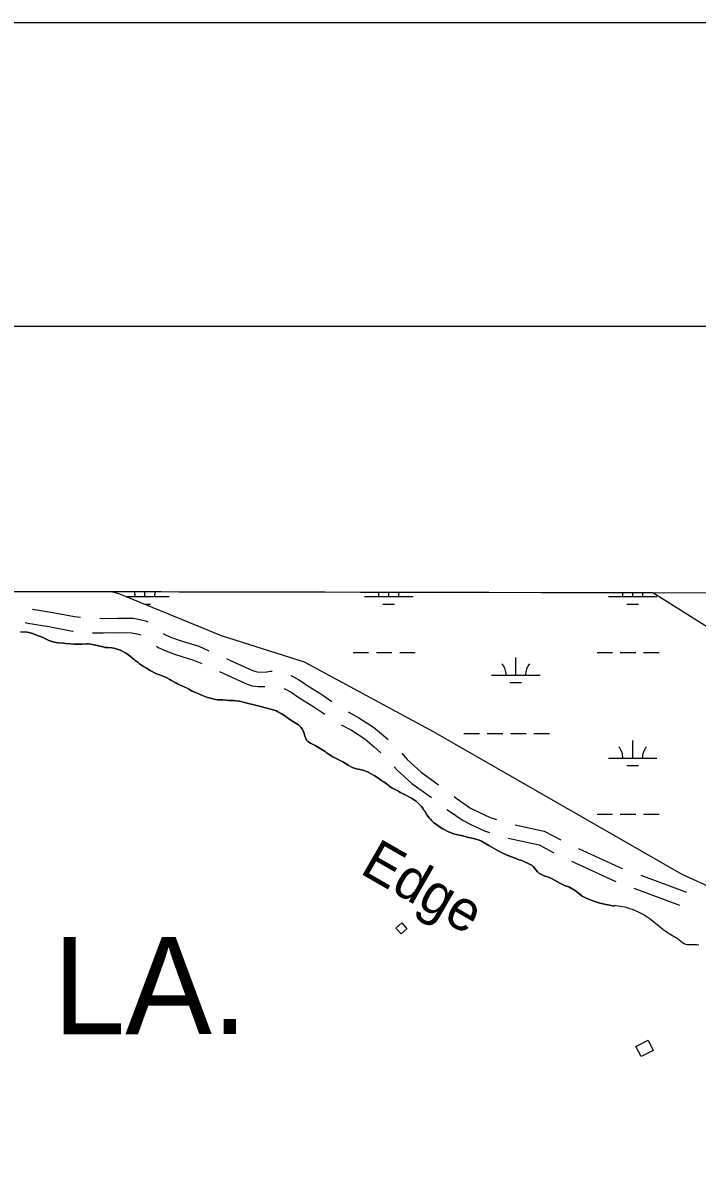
# Model space of a CAD drawing. Extents: x 3192927 to 3230760, y 831141 to 856475.
# Drawn here: x 3203837 to 3205224, y 853534 to 855891 of the extents above; entities that cross this region are included whole.
import ezdxf

# ---------------------------------------------------------------- set-up
doc = ezdxf.new("R2010")
doc.units = 0
for name, color, linetype in [('G-ANNO-NPLT', 7, 'Continuous'), ('V-ANNO-SYMB', 7, 'Continuous'), ('V-BLDG-OTLN', 7, 'Continuous'), ('V-GRID-FRAM', 7, 'Continuous'), ('V-RIVR-IDEN', 7, 'Continuous'), ('V-ROAD-CNTR', 7, 'Continuous'), ('V-SITE-VEGE', 7, 'Continuous'), ('V-TOPO-GNAM-IDEN', 7, 'Continuous'), ('V-TOPO-SHOR', 7, 'Continuous'), ('V-WETL-SWMP', 7, 'Continuous')]:
    doc.layers.add(name, color=color, linetype=linetype)

msp = doc.modelspace()

# ---------------------------------------------------------------- linework, layer by layer
at = {"layer": 'G-ANNO-NPLT'}
msp.add_lwpolyline([(3193509.9, 831724.7), (3230176.5, 831724.7), (3230176.5, 855891.4), (3193509.9, 855891.4)], close=True, dxfattribs=at)
at = {"layer": 'V-ANNO-SYMB'}
msp.add_lwpolyline([(3196260, 832349.8), (3229343.2, 832349.8), (3229343.2, 855266.3), (3196260, 855266.3), (3196260, 832349.8)], dxfattribs=at)
at = {"layer": 'V-BLDG-OTLN'}
for points in [[(3204604.9, 854027.6), (3204616.9, 854038.5), (3204627.2, 854025.9), (3204615.8, 854015.6)], [(3205098.7, 853784.2), (3205123.7, 853796.6), (3205134, 853775.9), (3205109.1, 853763.5)]]:
    msp.add_lwpolyline(points, close=True, dxfattribs=at)
at = {"layer": 'V-GRID-FRAM'}
msp.add_lwpolyline([(3197144.3, 854733.3), (3228527.7, 854674), (3228501.2, 836486.7), (3197102, 836546.1), (3197144.3, 854733.3)], dxfattribs=at)
at = {"layer": 'V-ROAD-CNTR'}
for p, q in [((3205108.8, 854136.4), (3205202.4, 854101.3)), ((3205094.4, 854109.8), (3205188.1, 854074.7))]:
    msp.add_line(p, q, dxfattribs=at)
for points in [[(3203856.9, 854684.3), (3203895.6, 854678.1), (3203943.4, 854669), (3203955.5, 854667.9)], [(3203995.4, 854665.5), (3204002.2, 854665.4), (3204032.3, 854666), (3204064.3, 854665.7), (3204078, 854663.2), (3204083, 854662), (3204089.9, 854660), (3204094.4, 854658.2)], [(3203842.2, 854656.7), (3203847.2, 854655.5), (3203890.5, 854648.5), (3203939.2, 854639.3), (3203940.6, 854639.1)], [(3203980.5, 854635.7), (3204002.3, 854635.4), (3204032.4, 854636), (3204061.4, 854635.7), (3204072, 854633.8), (3204075.3, 854633), (3204080, 854631.6), (3204080, 854631.6)], [(3204126.4, 854634.4), (3204130.5, 854631.4), (3204142.8, 854626), (3204160.5, 854619.6), (3204199, 854607.8), (3204219.5, 854598.7)], [(3204111.9, 854607.8), (3204115.6, 854605.2), (3204131.6, 854598.2), (3204151, 854591.1), (3204188.5, 854579.6), (3204205.1, 854572.3)], [(3204256, 854582.5), (3204264.6, 854578.7), (3204309.7, 854558.1), (3204316.4, 854555.7), (3204322.5, 854554.8), (3204339, 854555.6), (3204346.8, 854556.7), (3204350.2, 854556.7)], [(3204241.7, 854556.1), (3204252.3, 854551.4), (3204298.4, 854530.2), (3204309.2, 854526.5), (3204321, 854524.8), (3204335.3, 854525.4)], [(3204388.5, 854547.6), (3204390, 854547), (3204404.4, 854539.2), (3204421.6, 854527.6), (3204452.3, 854508.5), (3204473.1, 854494.5)], [(3204374.1, 854521), (3204377.3, 854519.7), (3204388.9, 854513.5), (3204405.2, 854502.5), (3204436, 854483.4), (3204458.7, 854468)], [(3204506.7, 854472.9), (3204528.7, 854460.7), (3204558.5, 854441.2), (3204579.3, 854423.9), (3204588.5, 854415.8)], [(3204492.4, 854446.5), (3204513.2, 854435), (3204540.6, 854417.1), (3204559.8, 854401.1), (3204573.8, 854388.8)], [(3204616.6, 854387.5), (3204628.1, 854374.5), (3204656.5, 854348.9), (3204692.5, 854322.9)], [(3204601.1, 854359.7), (3204606.8, 854353.3), (3204637.6, 854325.6), (3204678.1, 854296.3)], [(3204724.3, 854298.7), (3204730.7, 854293.7), (3204758.4, 854274.8), (3204773.7, 854267), (3204798.5, 854255.7), (3204811.6, 854251)], [(3204709.8, 854271.9), (3204712.9, 854269.5), (3204743.1, 854249), (3204760.6, 854240), (3204787.2, 854227.8), (3204797.2, 854224.3)], [(3204850.1, 854240.3), (3204909.6, 854227.2), (3204944.2, 854209.1)], [(3204835.5, 854212.8), (3204899.2, 854198.8), (3204930, 854182.7)], [(3204980.3, 854191.8), (3205063.8, 854153.3), (3205071.3, 854150.5)], [(3204966, 854165.3), (3205052.2, 854125.6), (3205057, 854123.8)]]:
    msp.add_lwpolyline(points, dxfattribs=at)
at = {"layer": 'V-SITE-VEGE'}
for p, q in [((3205133.2, 854718.2), (3203566.3, 854721.2)), ((3205617.6, 854411.2), (3205133.2, 854718.2)), ((3203832.4, 854637.6), (3203845.8, 854636.7)), ((3203845.8, 854636.7), (3203849.6, 854636.2)), ((3203849.6, 854636.2), (3203854.9, 854634.7)), ((3203854.9, 854634.7), (3203864.1, 854631.6)), ((3203864.1, 854631.6), (3203876.8, 854626.4)), ((3203876.8, 854626.4), (3203890.9, 854619.8)), ((3203890.9, 854619.8), (3203899, 854617)), ((3203899, 854617), (3203902, 854616.2)), ((3203902, 854616.2), (3203909.9, 854615.1)), ((3203909.9, 854615.1), (3203921.2, 854614)), ((3203921.2, 854614), (3203925, 854613.5)), ((3203925, 854613.5), (3203934.7, 854613)), ((3203934.7, 854613), (3203943.6, 854612.1)), ((3203958.6, 854612.3), (3203969.2, 854613)), ((3203969.2, 854613), (3203972.4, 854613)), ((3203972.4, 854613), (3203976.8, 854612.3)), ((3203943.6, 854612.1), (3203958.6, 854612.3)), ((3203976.8, 854612.3), (3203983.1, 854610.8)), ((3203983.1, 854610.8), (3203986.9, 854610)), ((3203986.9, 854610), (3203990, 854609.7)), ((3203990, 854609.7), (3204001.7, 854606.6)), ((3204001.7, 854606.6), (3204006.3, 854605.7)), ((3204006.3, 854605.7), (3204011.4, 854605.3)), ((3204011.4, 854605.3), (3204020, 854604.5)), ((3204020, 854604.5), (3204024.3, 854603.7)), ((3204024.3, 854603.7), (3204031.5, 854602)), ((3204031.5, 854602), (3204035.2, 854600.9)), ((3204035.2, 854600.9), (3204039.2, 854599.1)), ((3204039.2, 854599.1), (3204048.7, 854593.7)), ((3204048.7, 854593.7), (3204052.3, 854591.4)), ((3204052.3, 854591.4), (3204065.5, 854581.2)), ((3204065.5, 854581.2), (3204068.1, 854578.9)), ((3204068.1, 854578.9), (3204074.1, 854574.2)), ((3204074.1, 854574.2), (3204077.1, 854571.7)), ((3204077.1, 854571.7), (3204085.6, 854566.2)), ((3204085.6, 854566.2), (3204091.4, 854562.7)), ((3204091.4, 854562.7), (3204099.2, 854558.1)), ((3204099.2, 854558.1), (3204110.7, 854552.1)), ((3204110.7, 854552.1), (3204118, 854549.2)), ((3204118, 854549.2), (3204122, 854547.9)), ((3204122, 854547.9), (3204129.5, 854544.8)), ((3204129.5, 854544.8), (3204133.3, 854543)), ((3204133.3, 854543), (3204139.5, 854539.5)), ((3204139.5, 854539.5), (3204143.3, 854537.2)), ((3204143.3, 854537.2), (3204147.7, 854534.7)), ((3204147.7, 854534.7), (3204152, 854532.4)), ((3204152, 854532.4), (3204155.2, 854530.8)), ((3204155.2, 854530.8), (3204158.2, 854529.1)), ((3204158.2, 854529.1), (3204170.3, 854523.5)), ((3204170.3, 854523.5), (3204174.1, 854522.1)), ((3204174.1, 854522.1), (3204178.7, 854519.4)), ((3204178.7, 854519.4), (3204185.8, 854515.5)), ((3204185.8, 854515.5), (3204189, 854514)), ((3204189, 854514), (3204200.5, 854509.2)), ((3204200.5, 854509.2), (3204203.5, 854508.2)), ((3204203.5, 854508.2), (3204217, 854502.6)), ((3204217, 854502.6), (3204220.6, 854501.7)), ((3204220.6, 854501.7), (3204228.3, 854500)), ((3204228.3, 854500), (3204233.5, 854498.5)), ((3204233.5, 854498.5), (3204237.8, 854497.5)), ((3204237.8, 854497.5), (3204248.9, 854497.3)), ((3204248.9, 854497.3), (3204256.4, 854496.7)), ((3204256.4, 854496.7), (3204260, 854496.6)), ((3204260, 854496.6), (3204263.1, 854496.2)), ((3204263.1, 854496.2), (3204266.9, 854496.3)), ((3204266.9, 854496.3), (3204270.5, 854496.1)), ((3204270.5, 854496.1), (3204274.6, 854495.6)), ((3204274.6, 854495.6), (3204282.7, 854495.1)), ((3204282.7, 854495.1), (3204295.6, 854491.6)), ((3204295.6, 854491.6), (3204306.7, 854489)), ((3204306.7, 854489), (3204310.3, 854487.8)), ((3204310.3, 854487.8), (3204318, 854485.8)), ((3204318, 854485.8), (3204321.6, 854485)), ((3204321.6, 854485), (3204328.7, 854483.1)), ((3204328.7, 854483.1), (3204339, 854480.8)), ((3204339, 854480.8), (3204349.1, 854478)), ((3204349.1, 854478), (3204352.3, 854477.2)), ((3204352.3, 854477.2), (3204358.9, 854474.7)), ((3204358.9, 854474.7), (3204362, 854473.2)), ((3204362, 854473.2), (3204368.4, 854469.5)), ((3204368.4, 854469.5), (3204378.4, 854463.1)), ((3204378.4, 854463.1), (3204381.4, 854460.8)), ((3204381.4, 854460.8), (3204388.7, 854455.9)), ((3204388.7, 854455.9), (3204394.3, 854452)), ((3204394.3, 854452), (3204404.1, 854446)), ((3204404.1, 854446), (3204409.3, 854441.1)), ((3204409.3, 854441.1), (3204412.1, 854437.6)), ((3204412.1, 854437.6), (3204415.5, 854430.7)), ((3204415.5, 854430.7), (3204417.6, 854423.2)), ((3204417.6, 854423.2), (3204420.6, 854414.7)), ((3204420.6, 854414.7), (3204423.4, 854411.6)), ((3204423.4, 854411.6), (3204429.2, 854408.3)), ((3204429.2, 854408.3), (3204438.9, 854403.7)), ((3204438.9, 854403.7), (3204441.7, 854401.7)), ((3204441.7, 854401.7), (3204459, 854391)), ((3204459, 854391), (3204461.4, 854389.1)), ((3204461.4, 854389.1), (3204465.4, 854386.4)), ((3204465.4, 854386.4), (3204475.2, 854380.1)), ((3204475.2, 854380.1), (3204495.2, 854370.3)), ((3204495.2, 854370.3), (3204506.6, 854363.1)), ((3204506.6, 854363.1), (3204511, 854360.6)), ((3204511, 854360.6), (3204517.1, 854357.7)), ((3204517.1, 854357.7), (3204523.9, 854355.4)), ((3204523.9, 854355.4), (3204527.4, 854354.8)), ((3204527.4, 854354.8), (3204530.6, 854354.1)), ((3204530.6, 854354.1), (3204534.8, 854353.3)), ((3204534.8, 854353.3), (3204538.4, 854352.2)), ((3204538.4, 854352.2), (3204546.1, 854349.3)), ((3204546.1, 854349.3), (3204554, 854345.6)), ((3204554, 854345.6), (3204561.2, 854341.5)), ((3204561.2, 854341.5), (3204570.4, 854335.3)), ((3204570.4, 854335.3), (3204576.1, 854330.8)), ((3204576.1, 854330.8), (3204579.7, 854328.9)), ((3204579.7, 854328.9), (3204582.9, 854327)), ((3204582.9, 854327), (3204588.1, 854322.5)), ((3204588.1, 854322.5), (3204593.1, 854318.6)), ((3204593.1, 854318.6), (3204596.5, 854316.4)), ((3204596.5, 854316.4), (3204610, 854309.3)), ((3204610, 854309.3), (3204613.8, 854306.9)), ((3204613.8, 854306.9), (3204618.6, 854304.6)), ((3204618.6, 854304.6), (3204622.3, 854302.5)), ((3204622.3, 854302.5), (3204635.5, 854295.7)), ((3204635.5, 854295.7), (3204639, 854293.6)), ((3204639, 854293.6), (3204646.4, 854288.7)), ((3204646.4, 854288.7), (3204654.2, 854281.7)), ((3204654.2, 854281.7), (3204657.4, 854278)), ((3204657.4, 854278), (3204659.8, 854274.8)), ((3204659.8, 854274.8), (3204661.8, 854271.3)), ((3204661.8, 854271.3), (3204664, 854268.1)), ((3204664, 854268.1), (3204668.7, 854260.7)), ((3204668.7, 854260.7), (3204673.5, 854254.6)), ((3204673.5, 854254.6), (3204676.1, 854251.9)), ((3204676.1, 854251.9), (3204678.1, 854249.3)), ((3204678.1, 854249.3), (3204682.9, 854244.6)), ((3204682.9, 854244.6), (3204685.9, 854242.3)), ((3204685.9, 854242.3), (3204694.2, 854236.2)), ((3204694.2, 854236.2), (3204701, 854232.2)), ((3204701, 854232.2), (3204712.7, 854226)), ((3204712.7, 854226), (3204724.1, 854221.6)), ((3204724.1, 854221.6), (3204728.6, 854220.4)), ((3204728.6, 854220.4), (3204735.3, 854219.3)), ((3204735.3, 854219.3), (3204742.5, 854217.8)), ((3204742.5, 854217.8), (3204754, 854214.4)), ((3204754, 854214.4), (3204758.1, 854213.6)), ((3204758.1, 854213.6), (3204767.1, 854211.4)), ((3204767.1, 854211.4), (3204776.2, 854208.5)), ((3204776.2, 854208.5), (3204780.8, 854206.6)), ((3204780.8, 854206.6), (3204784.1, 854204.8)), ((3204784.1, 854204.8), (3204795.7, 854197.8)), ((3204795.7, 854197.8), (3204800.5, 854195.3)), ((3204800.5, 854195.3), (3204814.8, 854187)), ((3204814.8, 854187), (3204820.4, 854184.1)), ((3204820.4, 854184.1), (3204826.3, 854181.4)), ((3204826.3, 854181.4), (3204831.7, 854178.7)), ((3204831.7, 854178.7), (3204853.7, 854170.6)), ((3204853.7, 854170.6), (3204856.5, 854169.2)), ((3204856.5, 854169.2), (3204860.9, 854167.5)), ((3204860.9, 854167.5), (3204864, 854166.6)), ((3204864, 854166.6), (3204879.3, 854159.6)), ((3204879.3, 854159.6), (3204884.1, 854157.1)), ((3204884.1, 854157.1), (3204886.9, 854154.7)), ((3204886.9, 854154.7), (3204896.1, 854143.4)), ((3204896.1, 854143.4), (3204898.9, 854141)), ((3204898.9, 854141), (3204902.7, 854138.9)), ((3204902.7, 854138.9), (3204909.9, 854135.6)), ((3204909.9, 854135.6), (3204918.4, 854132.2)), ((3204918.4, 854132.2), (3204924.6, 854129.5)), ((3204924.6, 854129.5), (3204937.5, 854122.9)), ((3204937.5, 854122.9), (3204943.4, 854119.4)), ((3204943.4, 854119.4), (3204946.2, 854118.2)), ((3204946.2, 854118.2), (3204953.2, 854114.9)), ((3204953.2, 854114.9), (3204960.3, 854112.3)), ((3204960.3, 854112.3), (3204973.3, 854105.1)), ((3204973.3, 854105.1), (3204987.8, 854093.4)), ((3204987.8, 854093.4), (3204990.6, 854091.8)), ((3204990.6, 854091.8), (3204997.4, 854088.7)), ((3204997.4, 854088.7), (3205011.9, 854083.2)), ((3205011.9, 854083.2), (3205024, 854079.1)), ((3205024, 854079.1), (3205033.7, 854076.7)), ((3205033.7, 854076.7), (3205037, 854076.3)), ((3205037, 854076.3), (3205044.8, 854074.8)), ((3205044.8, 854074.8), (3205051.7, 854072.7)), ((3205051.7, 854072.7), (3205055.7, 854074.5)), ((3205055.7, 854074.5), (3205067.4, 854072.8)), ((3205067.4, 854072.8), (3205078.6, 854070.6)), ((3205078.6, 854070.6), (3205084.7, 854068.2)), ((3205084.7, 854068.2), (3205090.9, 854066.4)), ((3205090.9, 854066.4), (3205101.8, 854061.9)), ((3205101.8, 854061.9), (3205115.4, 854054.9)), ((3205115.4, 854054.9), (3205119.8, 854052.4)), ((3205119.8, 854052.4), (3205127.8, 854046.7)), ((3205127.8, 854046.7), (3205146.4, 854031.5)), ((3205146.4, 854031.5), (3205149.1, 854029.6)), ((3205149.1, 854029.6), (3205153.6, 854025.8)), ((3205153.6, 854025.8), (3205156.9, 854023.5)), ((3205156.9, 854023.5), (3205161.5, 854019.7)), ((3205161.5, 854019.7), (3205170.3, 854014.4)), ((3205170.3, 854014.4), (3205179, 854009.3)), ((3205179, 854009.3), (3205182.3, 854007.5)), ((3205182.3, 854007.5), (3205185.2, 854005.3)), ((3205185.2, 854005.3), (3205187.5, 854003.4)), ((3205187.5, 854003.4), (3205194.7, 853998.1)), ((3205194.7, 853998.1), (3205198, 853996.1)), ((3205198, 853996.1), (3205200.9, 853994.9)), ((3205200.9, 853994.9), (3205203.8, 853994.1)), ((3205203.8, 853994.1), (3205223.3, 853993.8)), ((3205223.3, 853993.8), (3205228, 853993.5))]:
    msp.add_line(p, q, dxfattribs=at)
at = {"layer": 'V-TOPO-SHOR'}
for points in [[(3204388.7, 854455.9), (3204381.4, 854460.8), (3204378.4, 854463.1), (3204368.4, 854469.5), (3204362, 854473.2), (3204358.9, 854474.7), (3204352.3, 854477.2), (3204349.1, 854478), (3204339, 854480.8), (3204328.7, 854483.1), (3204321.6, 854485), (3204318, 854485.8), (3204310.3, 854487.8), (3204306.7, 854489), (3204295.6, 854491.6), (3204282.7, 854495.1), (3204274.6, 854495.6), (3204270.5, 854496.1), (3204266.9, 854496.3), (3204263.1, 854496.2), (3204260, 854496.6), (3204256.4, 854496.7), (3204248.9, 854497.3), (3204237.8, 854497.5), (3204233.5, 854498.5), (3204228.3, 854500), (3204220.6, 854501.7), (3204217, 854502.6), (3204203.5, 854508.2), (3204200.5, 854509.2), (3204189, 854514), (3204185.8, 854515.5), (3204178.7, 854519.4), (3204174.1, 854522.1), (3204170.3, 854523.5), (3204158.2, 854529.1), (3204155.2, 854530.8), (3204152, 854532.4), (3204147.7, 854534.7), (3204143.3, 854537.2), (3204139.5, 854539.5), (3204133.3, 854543), (3204129.5, 854544.8), (3204122, 854547.9), (3204118, 854549.2), (3204110.7, 854552.1), (3204099.2, 854558.1), (3204091.4, 854562.7), (3204085.6, 854566.2), (3204077.1, 854571.7), (3204074.1, 854574.2), (3204068.1, 854578.9), (3204065.5, 854581.2), (3204052.3, 854591.4), (3204048.7, 854593.7), (3204039.2, 854599.1), (3204035.2, 854600.9), (3204031.5, 854602), (3204024.3, 854603.7), (3204020, 854604.5), (3204011.4, 854605.3), (3204006.3, 854605.7), (3204001.7, 854606.6), (3203990, 854609.7), (3203986.9, 854610), (3203983.1, 854610.8), (3203976.8, 854612.3), (3203972.4, 854613), (3203969.2, 854613), (3203958.6, 854612.3), (3203943.6, 854612.1), (3203934.7, 854613), (3203925, 854613.5), (3203921.2, 854614), (3203909.9, 854615.1), (3203902, 854616.2), (3203899, 854617), (3203890.9, 854619.8), (3203876.8, 854626.4), (3203864.1, 854631.6), (3203854.9, 854634.7), (3203849.6, 854636.2), (3203845.8, 854636.7), (3203832.4, 854637.6)], [(3205055.7, 854074.5), (3205051.7, 854072.7), (3205044.8, 854074.8), (3205037, 854076.3), (3205033.7, 854076.7), (3205024, 854079.1), (3205011.9, 854083.2), (3204997.4, 854088.7), (3204990.6, 854091.8), (3204987.8, 854093.4), (3204973.3, 854105.1), (3204960.3, 854112.3), (3204953.2, 854114.9), (3204946.2, 854118.2), (3204943.4, 854119.4), (3204937.5, 854122.9), (3204924.6, 854129.5), (3204918.4, 854132.2), (3204909.9, 854135.6), (3204902.7, 854138.9), (3204898.9, 854141), (3204896.1, 854143.4), (3204886.9, 854154.7), (3204884.1, 854157.1), (3204879.3, 854159.6), (3204864, 854166.6), (3204860.9, 854167.5), (3204856.5, 854169.2), (3204853.7, 854170.6), (3204831.7, 854178.7), (3204826.3, 854181.4), (3204820.4, 854184.1), (3204814.8, 854187), (3204800.5, 854195.3), (3204795.7, 854197.8), (3204784.1, 854204.8), (3204780.8, 854206.6), (3204776.2, 854208.5), (3204767.1, 854211.4), (3204758.1, 854213.6), (3204754, 854214.4), (3204742.5, 854217.8), (3204735.3, 854219.3), (3204728.6, 854220.4), (3204724.1, 854221.6), (3204712.7, 854226), (3204701, 854232.2), (3204694.2, 854236.2), (3204685.9, 854242.3), (3204682.9, 854244.6), (3204678.1, 854249.3), (3204676.1, 854251.9), (3204673.5, 854254.6), (3204668.7, 854260.7), (3204664, 854268.1), (3204661.8, 854271.3), (3204659.8, 854274.8), (3204657.4, 854278), (3204654.2, 854281.7), (3204646.4, 854288.7), (3204639, 854293.6), (3204635.5, 854295.7), (3204622.3, 854302.5), (3204618.6, 854304.6), (3204613.8, 854306.9), (3204610, 854309.3), (3204596.5, 854316.4), (3204593.1, 854318.6), (3204588.1, 854322.5), (3204582.9, 854327), (3204579.7, 854328.9), (3204576.1, 854330.8), (3204570.4, 854335.3), (3204561.2, 854341.5), (3204554, 854345.6), (3204546.1, 854349.3), (3204538.4, 854352.2), (3204534.8, 854353.3), (3204530.6, 854354.1), (3204527.4, 854354.8), (3204523.9, 854355.4), (3204517.1, 854357.7), (3204511, 854360.6), (3204506.6, 854363.1), (3204495.2, 854370.3), (3204475.2, 854380.1), (3204465.4, 854386.4), (3204461.4, 854389.1), (3204459, 854391), (3204441.7, 854401.7), (3204438.9, 854403.7), (3204429.2, 854408.3), (3204423.4, 854411.6), (3204420.6, 854414.7), (3204417.6, 854423.2), (3204415.5, 854430.7), (3204412.1, 854437.6), (3204409.3, 854441.1), (3204404.1, 854446), (3204394.3, 854452), (3204388.7, 854455.9)], [(3205055.7, 854074.5), (3205067.4, 854072.8), (3205078.6, 854070.6), (3205084.7, 854068.2), (3205090.9, 854066.4), (3205101.8, 854061.9), (3205115.4, 854054.9), (3205119.8, 854052.4), (3205127.8, 854046.7), (3205146.4, 854031.5), (3205149.1, 854029.6), (3205153.6, 854025.8), (3205156.9, 854023.5), (3205161.5, 854019.7), (3205170.3, 854014.4), (3205179, 854009.3), (3205182.3, 854007.5), (3205185.2, 854005.3), (3205187.5, 854003.4), (3205194.7, 853998.1), (3205198, 853996.1), (3205200.9, 853994.9), (3205203.8, 853994.1), (3205223.3, 853993.8), (3205228, 853993.5)]]:
    msp.add_lwpolyline(points, dxfattribs=at)
at = {"layer": 'V-WETL-SWMP'}
for p, q in [((3205133.2, 854718.2), (3204021.5, 854720.3)), ((3204021.5, 854720.3), (3204036.3, 854716.1)), ((3204036.3, 854716.1), (3204245, 854630.1)), ((3204050.4, 854710.3), (3204138.1, 854710.3)), ((3204088.1, 854710.3), (3204088.1, 854720.2)), ((3204540, 854710.3), (3204640, 854710.3)), ((3204590, 854710.3), (3204590, 854719.2)), ((3205041.9, 854710.3), (3205141.9, 854710.3)), ((3205091.9, 854710.3), (3205091.9, 854718.3)), ((3205617.6, 854411.2), (3205133.2, 854718.2)), ((3204087.8, 854694.9), (3204100.1, 854694.9)), ((3204578, 854694.9), (3204602, 854694.9)), ((3205079.9, 854694.9), (3205103.9, 854694.9)), ((3204245, 854630.1), (3204416, 854576.2)), ((3204516.6, 854594.9), (3204548.6, 854594.9)), ((3204564.6, 854594.9), (3204596.6, 854594.9)), ((3204612.6, 854594.9), (3204644.6, 854594.9)), ((3205018.5, 854594.9), (3205050.5, 854594.9)), ((3205066.5, 854594.9), (3205098.5, 854594.9)), ((3205114.5, 854594.9), (3205146.5, 854594.9)), ((3204416, 854576.2), (3204681.1, 854432.7)), ((3204851.4, 854548.5), (3204851.4, 854584.5)), ((3204801.4, 854548.5), (3204901.4, 854548.5)), ((3204839.4, 854533), (3204863.4, 854533)), ((3204681.1, 854432.7), (3205193, 854139)), ((3204744.6, 854428.4), (3204776.6, 854428.4)), ((3204792.6, 854428.4), (3204824.6, 854428.4)), ((3204840.6, 854428.4), (3204872.6, 854428.4)), ((3204888.6, 854428.4), (3204920.6, 854428.4)), ((3205091.9, 854377.6), (3205091.9, 854413.6)), ((3205041.9, 854377.6), (3205141.9, 854377.6)), ((3205079.9, 854362.2), (3205103.9, 854362.2)), ((3205018.5, 854262.2), (3205050.5, 854262.2)), ((3205066.5, 854262.2), (3205098.5, 854262.2)), ((3205114.5, 854262.2), (3205146.5, 854262.2)), ((3205193, 854139), (3205308.2, 854086.1))]:
    msp.add_line(p, q, dxfattribs=at)
for centre, start, end in [((3204032.8, 854710.8), 359.2282, 15.4963), ((3204143.3, 854710.8), 164.6394, 180.7718), ((3204534.7, 854710.8), 359.2282, 13.9005), ((3204645.2, 854710.8), 166.2326, 180.7718), ((3205036.6, 854710.8), 359.2282, 12.3158), ((3205147.1, 854710.8), 167.8151, 180.7718), ((3204796.2, 854548.9), 359.2282, 40.7718), ((3204906.6, 854548.9), 139.2282, 180.7718), ((3205036.6, 854378.1), 359.2282, 40.7718), ((3205147.1, 854378.1), 139.2282, 180.7718)]:
    msp.add_arc(centre, 35.2, start, end, dxfattribs=at)

# ---------------------------------------------------------------- texts
at = {"layer": 'V-RIVR-IDEN'}
msp.add_text('Edge', height=83, rotation=330.141, dxfattribs=at).set_placement((3204528.2, 854141.8))
at = {"layer": 'V-TOPO-GNAM-IDEN'}
msp.add_text('LA.', height=200, rotation=0.047, dxfattribs=at).set_placement((3203899, 853809.1))

doc.saveas('drawing.dxf')
